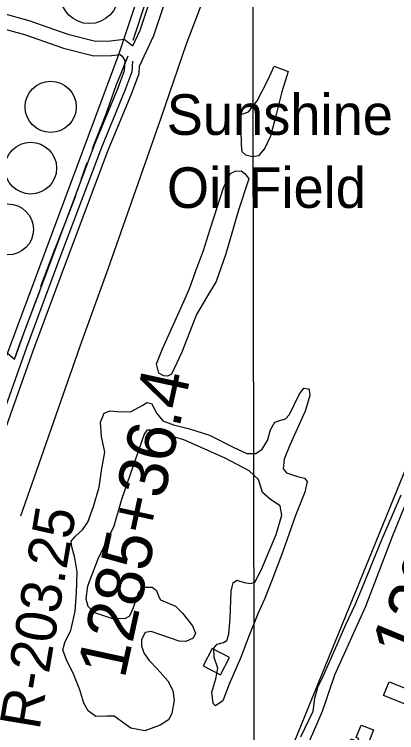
# Model space of a CAD drawing. Extents: x 3329332 to 3367211, y 631066 to 656469.
# Drawn here: x 3338207 to 3338989, y 649803 to 651272 of the extents above; entities that cross this region are included whole.
import ezdxf

# ---------------------------------------------------------------- set-up
doc = ezdxf.new("R2010")
doc.units = 0
for name, color, linetype in [('V-BLDG-IDEN', 7, 'Continuous'), ('V-BLDG-OTLN', 7, 'Continuous'), ('V-DOMW-TANK', 7, 'Continuous'), ('V-GRID-MAJR', 7, 'Continuous'), ('V-RIVR-RANG-IDEN', 7, 'Continuous'), ('V-ROAD-CNTR', 7, 'Continuous'), ('V-SITE-OTLN', 7, 'Continuous'), ('V-SITE-VEGE', 7, 'Continuous'), ('V-SURV-IDEN', 7, 'Continuous'), ('V-TOPO-SHOR', 7, 'Continuous')]:
    doc.layers.add(name, color=color, linetype=linetype)

msp = doc.modelspace()

# ---------------------------------------------------------------- linework, layer by layer
at = {"layer": 'V-BLDG-OTLN'}
for points in [[(3338592.741777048, 649939.9700933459), (3338628.229706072, 649921.5121302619), (3338646.6866691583, 649957.0000592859), (3338611.1997401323, 649975.457022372)], [(3338973.451, 649907.42), (3339019.6010000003, 649888.519), (3339008.1750000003, 649860.625), (3338962.028, 649879.5260000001)], [(3338915.829, 649728.2490000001), (3338877.251, 649742.964), (3338895.3340000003, 649790.375), (3338908.773, 649785.2490000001), (3338911.1350000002, 649791.4400000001), (3338906.076, 649793.3690000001), (3338915.724, 649818.66), (3338940.9390000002, 649809.04), (3338930.89, 649782.6950000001), (3338924.5470000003, 649785.1140000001), (3338922.389, 649779.451), (3338933.7120000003, 649775.132)]]:
    msp.add_lwpolyline(points, close=True, dxfattribs=at)
at = {"layer": 'V-DOMW-TANK'}
for centre, radius in [((3338360.2013498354, 651312.3704955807), 59.35760165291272), ((3338280.952869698, 651082.7555782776), 52.39614586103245), ((3338240.245628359, 650957.4500719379), 52.8947480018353), ((3338193.3709002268, 650832.2113166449), 52.236251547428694)]:
    msp.add_circle(centre, radius, dxfattribs=at)
at = {"layer": 'V-GRID-MAJR'}
msp.add_spline([(3338718.6920000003, 636457.969), (3338708.998, 642517.371), (3338699.3000000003, 648578.71), (3338689.602, 654640.072), (3338689.599, 654641.984)], degree=3, dxfattribs=at)
at = {"layer": 'V-ROAD-CNTR'}
for points in [[(3338462.542037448, 651165.648641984), (3338491.7459790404, 651228.3575165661), (3338540.4688815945, 651374.70522387), (3338581.951798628, 651495.9739813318), (3338617.484727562, 651587.5137982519), (3338635.3206918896, 651638.0626971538), (3338633.1276962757, 651660.53465221), (3338617.068728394, 651675.9206214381)], [(3338448.998064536, 651207.6275580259), (3338463.824034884, 651239.463494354), (3338512.042938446, 651384.2992046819), (3338553.763855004, 651506.2619607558), (3338589.348783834, 651597.935777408), (3338604.8167528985, 651641.7706897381), (3338604.349753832, 651646.560680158), (3338596.3147699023, 651654.2566647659)], [(3338219.855, 650246.348), (3338256.795, 650351.461), (3338302.142, 650482.134), (3338344.953, 650602.909), (3338398.662, 650751.708), (3338451.134, 650900.928), (3338506.966, 651060.041), (3338558.627, 651211.742), (3338628.22, 651394.321)], [(3338043.7518750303, 651296.33038062), (3338061.6398392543, 651288.3413965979), (3338092.073778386, 651277.0784191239), (3338129.5637034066, 651275.8814215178), (3338182.1205982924, 651274.181424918), (3338236.5274894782, 651259.1964548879), (3338315.877330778, 651231.5305102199), (3338372.983216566, 651216.867539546), (3338403.4621556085, 651217.4985382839), (3338431.4510996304, 651221.014531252), (3338448.998064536, 651207.6275580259)], [(3338034.0358944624, 651267.813437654), (3338050.3038619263, 651260.5474521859), (3338086.2377900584, 651247.2484787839), (3338128.599705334, 651245.8974814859), (3338177.588607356, 651244.311484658), (3338227.5955073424, 651230.538512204), (3338307.193348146, 651202.786567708), (3338369.499223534, 651186.7895997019), (3338405.648151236, 651187.536598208), (3338423.0131165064, 651189.718593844), (3338427.12110829, 651186.5846001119), (3338433.09609634, 651175.872621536), (3338433.1770961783, 651177.237618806)], [(3338448.1510662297, 651176.35062058), (3338446.835068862, 651154.1886649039), (3338432.687097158, 651116.406740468), (3338384.6771931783, 650999.6639739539), (3338299.2323640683, 650772.4064284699), (3338231.45649962, 650590.8947914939), (3338185.224592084, 650460.189052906), (3338116.4277296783, 650265.2534427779), (3338054.73185307, 650093.289786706), (3338039.5548834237, 650043.200886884), (3338026.4189096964, 650019.9609333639), (3338023.22691608, 650013.0049472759), (3337932.0060985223, 650041.746889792), (3337705.226552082, 650107.5167582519), (3337635.868690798, 650127.048719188)], [(3338207.0735483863, 650566.9398394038), (3338217.358527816, 650596.0197812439), (3338285.1863921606, 650777.6694179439), (3338370.717221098, 651005.156962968), (3338418.7231250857, 651121.8907294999), (3338431.9950985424, 651157.3326586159), (3338433.1770961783, 651177.2396188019)], [(3337645.1466722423, 650108.85275558), (3337701.1045603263, 650093.093787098), (3337927.6631072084, 650027.3889185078), (3338031.3408998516, 649994.7219838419), (3338039.7878829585, 650013.129947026), (3338053.429855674, 650037.263898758), (3338068.9778245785, 650088.578796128), (3338130.5597014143, 650260.2244528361), (3338199.367563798, 650455.1920628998), (3338245.5544714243, 650585.769801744), (3338313.2783359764, 650767.1434389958), (3338398.6371652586, 650994.1709849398), (3338446.65106923, 651110.922751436), (3338461.675039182, 651151.044671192), (3338462.542037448, 651165.648641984)], [(3337847.313267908, 650717.9095374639), (3337920.039122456, 650690.463592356), (3338078.270805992, 650628.035717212), (3338155.8746507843, 650599.97177334), (3338192.3105779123, 650579.7568137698), (3338207.0735483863, 650566.9398394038)]]:
    msp.add_lwpolyline(points, dxfattribs=at)
at = {"layer": 'V-SITE-OTLN'}
msp.add_lwpolyline([(3338401.7830000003, 651911.888), (3338652.855, 651887.789), (3338420.387, 651191.2930000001), (3338021.826, 650122.405), (3337704.941, 650232.36), (3337698.651, 650263.66), (3337860.093, 650739.002), (3337849.867, 650744.223), (3337538.139, 650840.1900000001), (3337706.815, 651360.849), (3337932.1010000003, 652020.7490000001), (3337976.106, 652090.281), (3338174.305, 651970.534), (3338329.316, 651926.046)], close=True, dxfattribs=at)
at = {"layer": 'V-SITE-VEGE'}
for points in [[(3338766.949, 651154.785), (3338753.646, 651113.272), (3338742.296, 651066.998), (3338730.561, 651023.099), (3338719.329, 650998.21), (3338706.171, 650982.4400000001), (3338693.486, 650980.531), (3338680.036, 650983.777), (3338672.551, 650990.947), (3338671.443, 651005.216), (3338670.437, 651037.3), (3338663.419, 651056.748), (3338666.241, 651065.843), (3338685.6890000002, 651072.861), (3338703.64, 651095.336), (3338725.668, 651138.385), (3338738.099, 651165.644)], [(3338686.103, 650935.817), (3338665.1410000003, 650871.377), (3338639.287, 650782.006), (3338619.561, 650725.482), (3338599.575, 650693.117), (3338579.179, 650658.379), (3338549.034, 650580.917), (3338527.788, 650535.886), (3338520.241, 650531.966), (3338512.721, 650532.802), (3338502.057, 650538.012), (3338497.41, 650557.05), (3338509.864, 650588.268), (3338553.5870000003, 650685.058), (3338564.824, 650711.533), (3338580.518, 650755.012), (3338593.785, 650789.3960000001), (3338607.097, 650832.492), (3338615.559, 650858.1900000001), (3338634.915, 650919.077), (3338648.532, 650946.328), (3338658.463, 650951.0260000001), (3338670.349, 650951.751), (3338678.636, 650946.158)]]:
    msp.add_lwpolyline(points, close=True, dxfattribs=at)
for points in [[(3338477.952, 650478.339), (3338487.449, 650476.305), (3338498.4220000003, 650455.647), (3338510.616, 650440.924), (3338531.9560000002, 650432.486), (3338564.785, 650424.378), (3338605.903, 650411.474), (3338654.481, 650387.037), (3338682.531, 650373.807), (3338700.355, 650374.104), (3338713.472, 650382.743), (3338724.269, 650400.902), (3338730.7290000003, 650422.251), (3338739.136, 650438.049), (3338749.849, 650441.553), (3338761.352, 650444.656), (3338769.325, 650453.72), (3338789.361, 650494.799), (3338798.937, 650507.421), (3338808.438, 650506.178), (3338810.011, 650504.189), (3338810.736, 650492.302), (3338801.839, 650460.667), (3338770.157, 650390.74), (3338758.514, 650362.685), (3338756.421, 650342.893), (3338763.503, 650334.535), (3338785.642, 650327.281), (3338799.877, 650323.24), (3338805.384, 650316.475), (3338800.5100000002, 650295.115), (3338781.6210000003, 650246.9010000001), (3338755.86, 650173.376), (3338734.947, 650117.647), (3338718.473, 650076.153), (3338704.44, 650046.131), (3338687.5670000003, 650003.846), (3338669.469, 649955.231), (3338646.197, 649902.29), (3338632.934, 649868.301), (3338617.826, 649858.088), (3338613.1, 649862.868), (3338610.46, 649886.252), (3338618.93, 649913.534), (3338622.6210000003, 649935.2980000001)], [(3338622.6210000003, 649935.2980000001), (3338615.215, 649956.726), (3338614.924, 649975.7390000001), (3338621.31, 649984.022), (3338634.401, 649987.511), (3338641.157, 649991.831), (3338645.19, 650004.481), (3338648.147, 650036.547), (3338650.441, 650092.777), (3338654.103, 650109.787), (3338661.66, 650115.29), (3338676.686, 650110.453), (3338689.74, 650108.001), (3338698.8680000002, 650111.118), (3338711.678, 650135.207), (3338742.1950000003, 650208.704), (3338753.508, 650248.25), (3338750.051, 650267.278), (3338730.321, 650280.064), (3338714.162, 650294.414), (3338706.39, 650320.995), (3338687.082, 650338.532), (3338637.719, 650364.159), (3338553.5700000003, 650402.262), (3338485.554, 650421.659), (3338477.631, 650421.704), (3338472.441, 650413.811), (3338425.736, 650279.806), (3338409.981, 650225.237), (3338377.518, 650157.692), (3338356.612, 650102.756), (3338352.901, 650077.032), (3338357.171, 650061.561), (3338370.963, 650049.205), (3338405.357, 650037.524), (3338433.076, 650036.5750000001), (3338443.009, 650042.064), (3338450.63, 650059.052), (3338461.507, 650091.47), (3338471.859, 650100.915), (3338488.4930000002, 650100.821), (3338497.5640000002, 650093.6410000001), (3338502.2430000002, 650080.939), (3338505.379, 650074.981), (3338536.592, 650061.735), (3338550.773, 650047.792), (3338571.222, 650021.93), (3338577.077, 650006.451), (3338572.267, 649996.181), (3338557.572, 649989.531), (3338543.715, 649990.4010000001), (3338523.95, 649997.246), (3338506.161, 650003.287), (3338486.396, 650010.134), (3338474.4990000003, 650007.823), (3338466.895, 649994.004), (3338466.819, 649980.143), (3338472.279, 649965.059), (3338482.099, 649950.746), (3338499.427, 649933.221), (3338520.68, 649908.9400000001), (3338530.864, 649889.078), (3338533.5270000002, 649869.655), (3338529.017, 649842.351), (3338521.8140000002, 649829.719), (3338504.719, 649818.328), (3338473.369, 649807.019), (3338445.278, 649812.725), (3338425.943, 649825.904), (3338410.9560000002, 649837.08), (3338396.302, 649837.162), (3338373.326, 649836.498), (3338357.548, 649848.0750000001), (3338348.9220000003, 649863.571), (3338340.361, 649890.553), (3338328.6550000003, 649921.513), (3338313.379, 649952.095), (3338305.576, 649972.735), (3338310.4220000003, 649989.3420000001), (3338322.038, 650012.247), (3338331.369, 650051.409), (3338333.955, 650089.0210000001), (3338335.387, 650131.789), (3338330.4, 650160.336), (3338324.19, 650182.946), (3338322.6750000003, 650194.837), (3338332.241, 650205.478), (3338345.774, 650217.68), (3338356.9560000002, 650233.853), (3338368.622, 650265.474), (3338380.33, 650305.017), (3338385.698, 650343.405), (3338391.432, 650377.039), (3338384.879, 650408.76), (3338382.669, 650438.084), (3338390.298, 650456.657), (3338402.207, 650461.341), (3338417.247, 650459.672), (3338444.578, 650459.518), (3338470.796, 650473.629), (3338477.952, 650478.339)], [(3339045.688, 650366.604), (3338980.22, 650205.773), (3338924.744, 650061.127), (3338861.3680000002, 649920.48), (3338836.393, 649846.556), (3338803.082, 649769.508)], [(3338792.926, 649794.518), (3338817.7830000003, 649847.453), (3338821.1010000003, 649873.9720000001), (3338827.5640000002, 649896.113), (3338839.184, 649919.813), (3338862.057, 649972.36), (3338884.927, 650024.1190000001), (3338903.77, 650064.807), (3338921.0330000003, 650105.505), (3338939.5100000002, 650150.9500000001), (3338958.796, 650199.557), (3338979.262, 650246.573), (3338997.724, 650289.643)]]:
    msp.add_lwpolyline(points, dxfattribs=at)
at = {"layer": 'V-TOPO-SHOR'}
for p, q in [((3338757.4405332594, 649730.8316572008), (3339617.6586096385, 651840.4733818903)), ((3338343.272, 650934.558), (3338355.4450000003, 650969.185))]:
    msp.add_line(p, q, dxfattribs=at)
for points in [[(3338449.792, 651219.365), (3338475.791, 651297.705), (3338506.608, 651383.473), (3338541.3850000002, 651481.665), (3338570.227, 651561.9990000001), (3338601.33, 651649.306)], [(3338366.344, 650997.6240000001), (3338394.775, 651068.337), (3338414.935, 651126.556), (3338439.282, 651186.794)], [(3338261.0810000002, 650716.1140000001), (3338288.9790000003, 650789.721), (3338307.128, 650835.895), (3338333.181, 650903.225)], [(3338207.788, 650568.136), (3338230.14, 650631.003), (3338258.544, 650705.802)]]:
    msp.add_lwpolyline(points, dxfattribs=at)

# ---------------------------------------------------------------- texts
at = {"layer": 'V-BLDG-IDEN'}
for s, p in [('Sunshine', (3338518.2388341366, 651025.4887325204)), ('Oil Field', (3338518.7233906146, 650876.1012143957))]:
    msp.add_text(s, height=82.99983200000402, dxfattribs=at).set_placement(p)
at = {"layer": 'V-RIVR-RANG-IDEN'}
msp.add_text('R-203.25', height=82.99999800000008, rotation=80.4516786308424, dxfattribs=at).set_placement((3338257.8058101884, 649806.8488794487))
at = {"layer": 'V-SURV-IDEN'}
for s, rotation, p in [('1291+09.3', 67.66840037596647, (3339025.765262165, 649943.1674586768)), ('1285+36.4', 77.70051126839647, (3338432.1400158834, 649911.5898696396))]:
    msp.add_text(s, height=100.00000000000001, rotation=rotation, dxfattribs=at).set_placement(p)

doc.saveas('drawing.dxf')
